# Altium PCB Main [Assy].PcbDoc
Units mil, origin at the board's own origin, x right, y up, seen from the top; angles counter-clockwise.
Board outline 6300 x 4291.34 mil, 4 copper layers (Top Layer, MidLayer1, MidLayer2, Bottom Layer), stack 62.529 mil thick; 0 components, 266 nets, 0 pads, 0 vias.
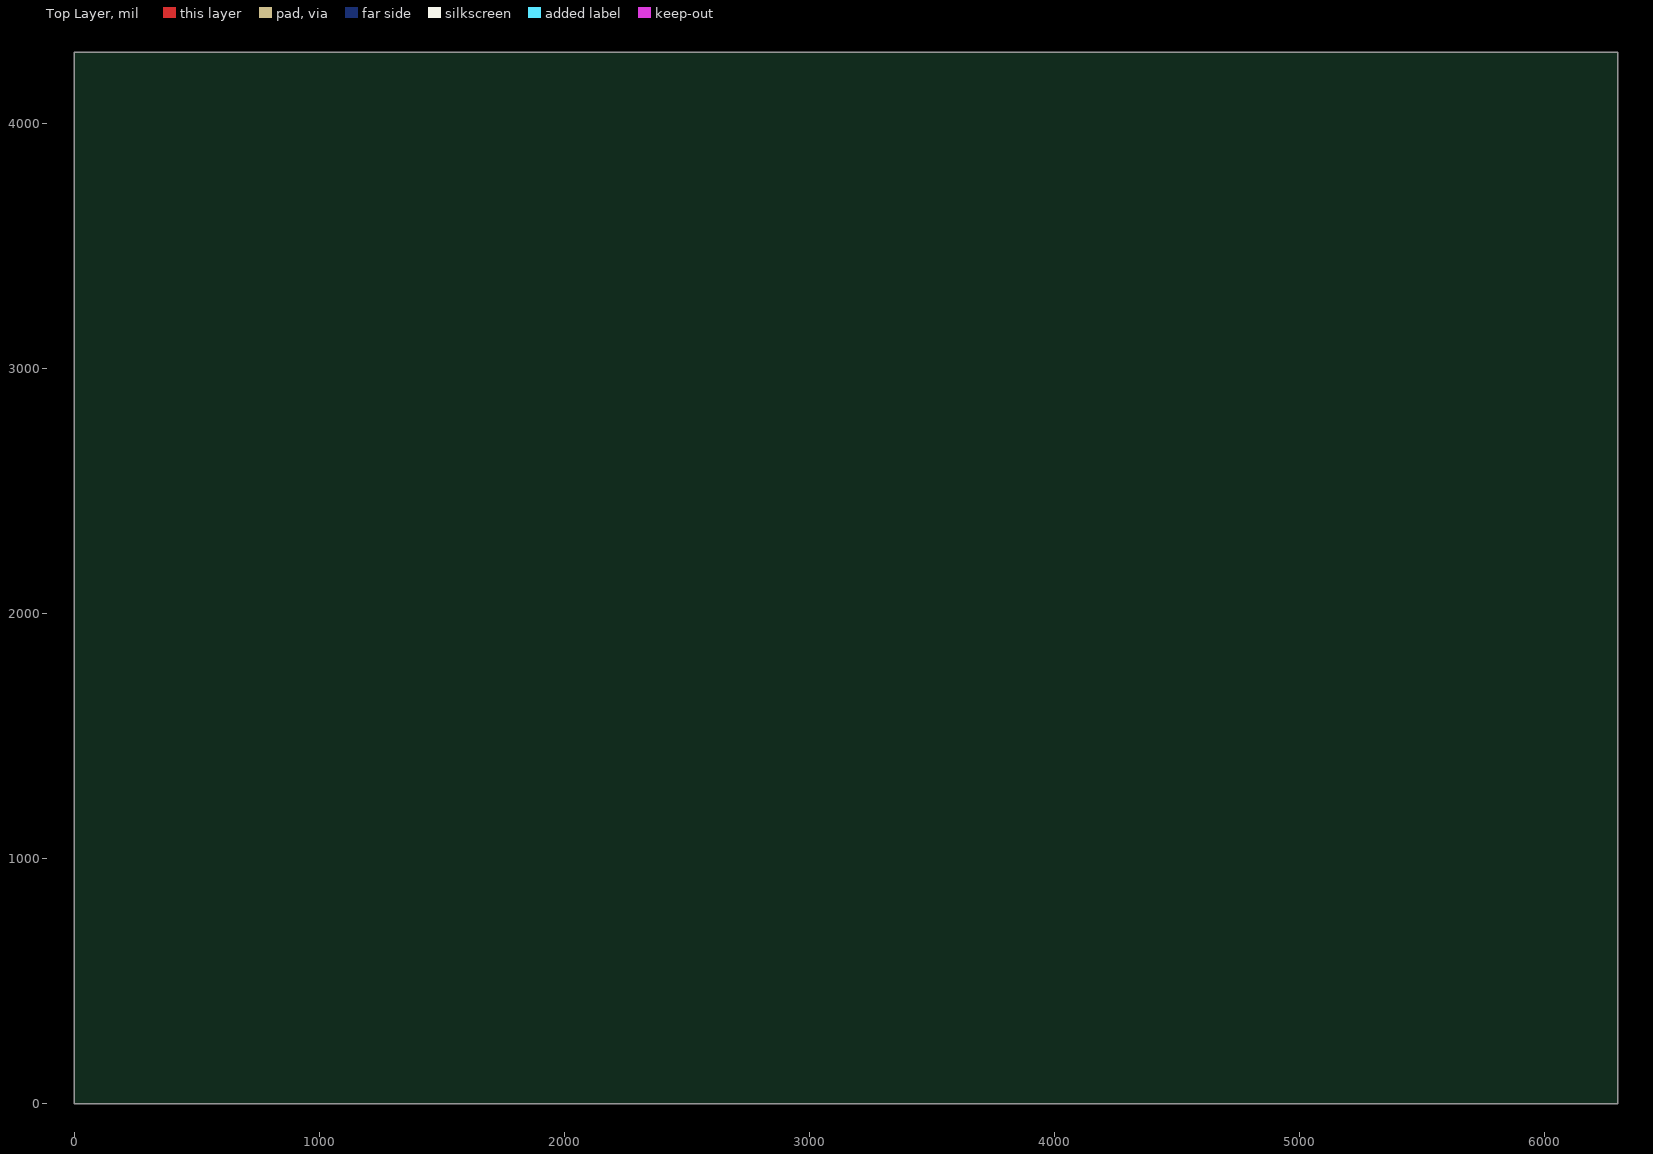
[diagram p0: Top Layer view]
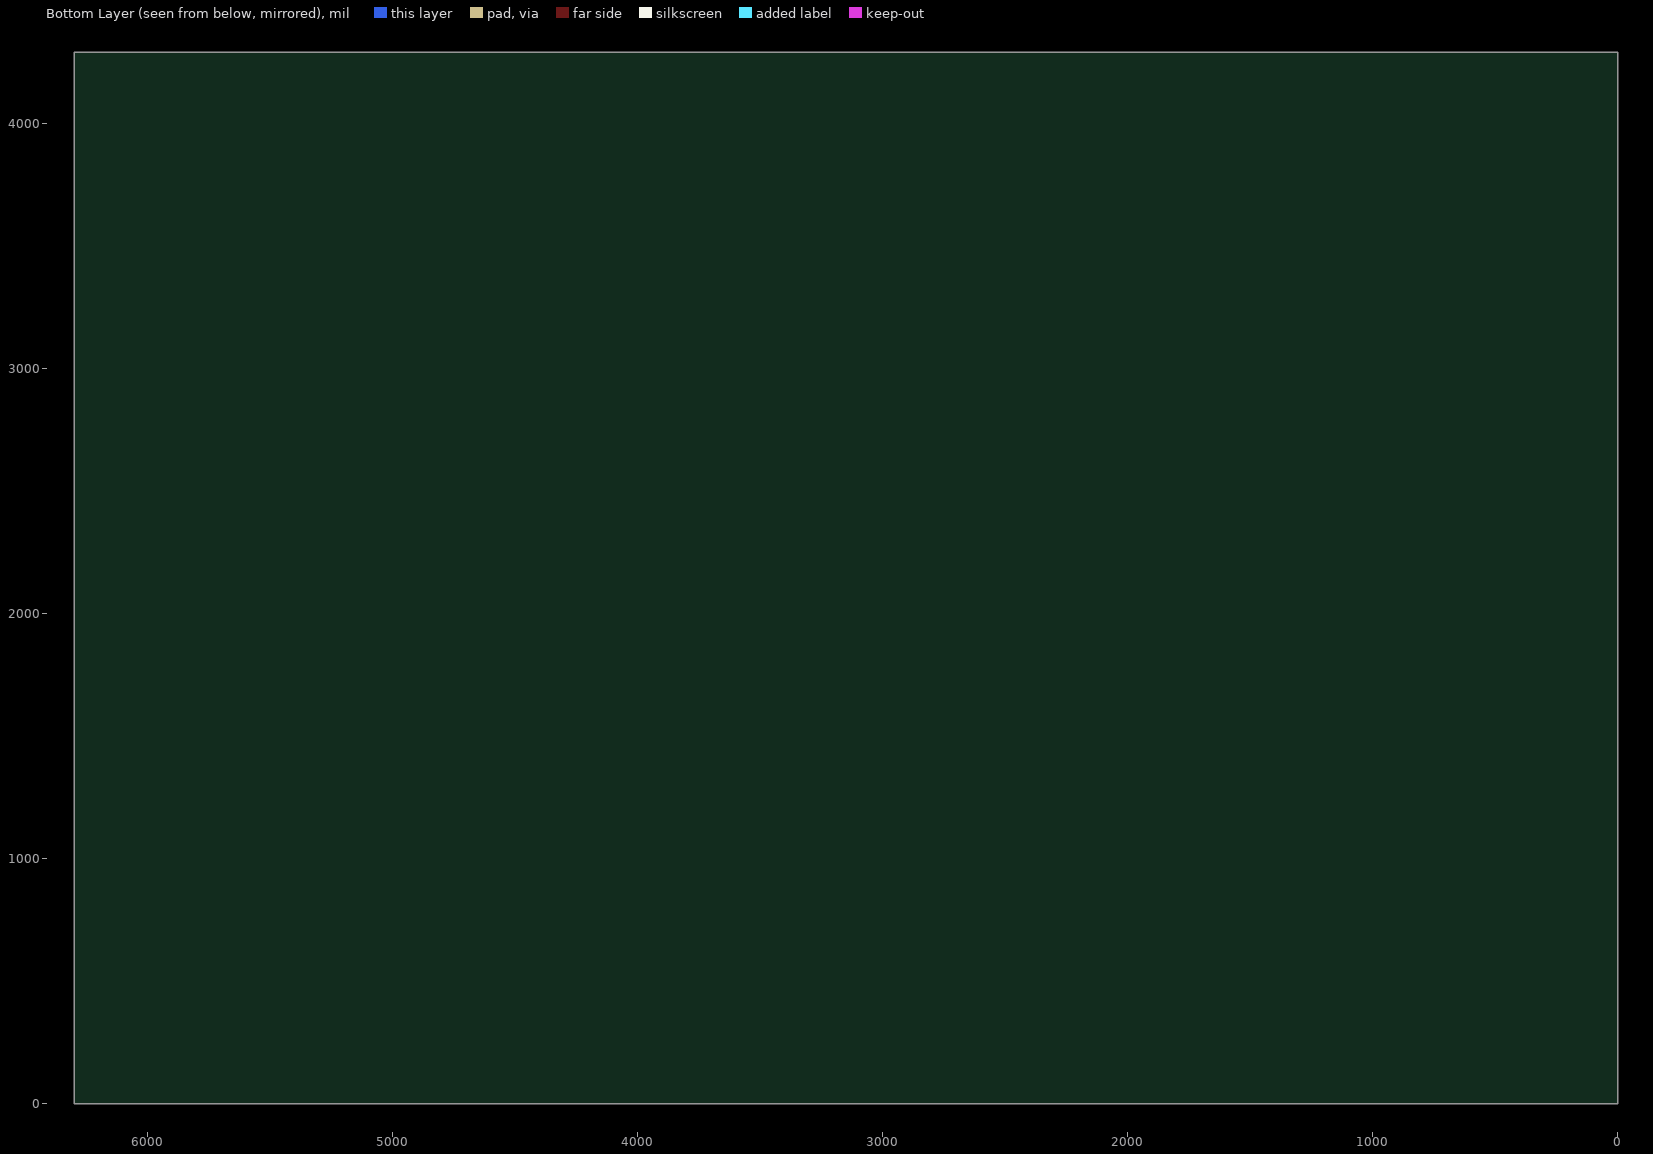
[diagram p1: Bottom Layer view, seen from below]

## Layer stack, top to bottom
Top Layer: signal copper 1.4
Dielectric: prepreg 9.3701, FR-4, Dk 4.2
MidLayer1: signal copper 1.4
Dielectric: core 38.189, FR-4, Dk 4.8
MidLayer2: signal copper 1.4
Dielectric: prepreg 9.3701, FR-4, Dk 4.8
Bottom Layer: signal copper 1.4

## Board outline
0,0 0,4291.34 6300,4291.34 6300,0

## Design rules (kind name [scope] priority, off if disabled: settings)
Clearance Clearance_1 [InNamedPolygon('Top - GND')] p1: gap=7
Clearance [All] p2: gap=7
FabricationTestPointUsage TestPointUsage [All] p1: valid=0 allowmultiple=FALSE
FabricationTestpoint Testpoint [All] p1: side=3 testpointundercomponent=TRUE minsize=40 maxsize=100 preferedsize=60 minholesize=0 maxholesize=40 preferedholesize=32 testpointgrid=1 allowsidetop=TRUE allowsidebottom=TRUE usegrid=TRUE gridtolerance=0.01
HoleSize [All] p1: absolutevalues=TRUE maxlimit=196.85 minlimit=9.84 maxpercent=80.000 minpercent=20.000
PlaneClearance [All] p1: clearance=19.68
PolygonConnect PolygonConnectVia [All vs isvia] p1: connectstyle=Direct reliefconductorwidth=9.84 reliefentries=4 polygonreliefangle="90 Angle" airgapwidth=10
PolygonConnect [All] p2: connectstyle=Relief reliefconductorwidth=15.75 reliefentries=4 polygonreliefangle="90 Angle" airgapwidth=10
RoutingCorners [All] p1: cornerstyle=45-Degree minsetback=98.43 maxsetback=98.43
RoutingLayers [All] p1: top layer_v5=TRUE mid layer 1_v5=FALSE mid layer 2_v5=FALSE bottom layer_v5=TRUE
RoutingVias [All] p1: holewidth=11.81 width=27.56 viastyle="Through Hole" minholewidth=11.81 minwidth=27.56 maxholewidth=11.81 maxwidth=27.56
SilkToSolderMaskClearance SilkscreenOverComponentPads [IsPad] p1: minsilkscreentomaskgap=10 clearancetoexposedcopper=TRUE
SolderMaskExpansion [All] p1: expansion=1.97
Width "Width_High Power" [InNetClass('High Power')] p1: maxlimit=59.06 minlimit=19.68 preferedwidth=39.37
Width Width_Power [InNetClass('Power')] p2: maxlimit=39.37 minlimit=11.81 preferedwidth=19.68
Width [All] p3: maxlimit=100 minlimit=7 preferedwidth=8
21 further rules are at their usual default settings.

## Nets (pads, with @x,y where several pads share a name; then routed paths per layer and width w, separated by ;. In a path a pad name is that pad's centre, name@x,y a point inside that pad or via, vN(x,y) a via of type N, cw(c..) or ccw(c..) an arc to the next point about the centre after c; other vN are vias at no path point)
3V3: 
3V3A: 
3V3UC: 
3V3USB: 
+5V: 
+5VUSB: 
BUZZER: 
C1: 
C2: 
C3: 
DIGI_ANODE1: 
DIGI_ANODE2: 
DIGI_ANODE3: 
DIGI_ANODE4: 
DIGI_CATHODE1: 
DIGI_CATHODE2: 
DIGI_CATHODE3: 
DIGI_CATHODE4: 
GND: 
ICD_NMCLR: 
IDC_PGC: 
IDC_PGD: 
NetANT_1: 
NetBUZ1_1: 
NetBUZ1_2: 
NetC2_1: 
NetC3_1: 
NetC5_1: 
NetC5_2: 
NetC8_1: 
NetC8_2: 
NetC30_1: 
NetC31_1: 
NetC32_1: 
NetC33_1: 
NetC34_1: 
NetC35_1: 
NetC36_1: 
NetC37_1: 
NetC38_1: 
NetC39_1: 
NetC40_1: 
NetC41_1: 
NetC42_1: 
NetC43_1: 
NetC45_1: 
NetC67_1: 
NetC68_1: 
NetC69_1: 
NetC78_1: 
NetC79_1: 
NetC80_1: 
NetC83_1: 
NetC84_1: 
NetC85_1: 
NetC86_1: 
NetD1_1: 
NetD2_1: 
NetD6_1: 
NetD10_1: 
NetD15_2: 
NetD16_2: 
NetD18_2: 
NetD19_3: 
NetD21_2: 
NetD23_2: 
NetGPS1_9: 
NetGPS1_20: 
NetGPS1_21: 
NetGPS1_22: 
NetJ5_2: 
NetJ5_3: 
NetJ7_2: 
NetJ7_3: 
NetJ8_2: 
NetJ8_3: 
NetJ11_1: 
NetLCD1_3: 
NetLCD1_4: 
NetLCD1_5: 
NetLCD1_6: 
NetLCD1_7: 
NetLCD1_8: 
NetLCD1_9: 
NetLCD1_10: 
NetLCD1_11: 
NetLCD1_12: 
NetLCD1_13: 
NetLCD1_14: 
NetLCD1_15: 
NetLCD1_16: 
NetLCD1_17: 
NetLCD-SPR1_1: 
NetLCD-SPR2_1: 
NetLED1_2: 
NetLED2_2: 
NetLED3_2: 
NetLED4_1: 
NetLED5_1: 
NetP2_1: 
NetP2_2: 
NetP2_3: 
NetP2_4: 
NetP2_5: 
NetP2_6: 
NetP3_9: 
NetP3_10: 
NetP3_11: 
NetP3_14: 
NetP3_15: 
NetP3_16: 
NetP3_17: 
NetP3_18: 
NetP3_19: 
NetP3_20: 
NetP3_21: 
NetP3_22: 
NetP3_23: 
NetP3_24: 
NetP3_25: 
NetP3_26: 
NetP3_27: 
NetP3_28: 
NetP3_29: 
NetP3_30: 
NetP3_31: 
NetP3_32: 
NetP3_33: 
NetP3_34: 
NetP4_9: 
NetP4_10: 
NetP4_11: 
NetP4_12: 
NetP4_13: 
NetP4_14: 
NetP4_15: 
NetP4_16: 
NetP4_17: 
NetP4_18: 
NetP4_19: 
NetP4_20: 
NetP4_21: 
NetP4_22: 
NetP4_23: 
NetP4_24: 
NetP4_25: 
NetP4_26: 
NetP4_27: 
NetP4_28: 
NetP4_29: 
NetP4_30: 
NetP4_31: 
NetP4_32: 
NetP4_33: 
NetP5_2: 
NetP5_4: 
NetQ1_1: 
NetQ2_1: 
NetQ3_1: 
NetQ4_1: 
NetQ4_3: 
NetQ5_1: 
NetQ6_1: 
NetQ6_3: 
NetQ7_1: 
NetQ8_1: 
NetQ8_3: 
NetQ9_1: 
NetQ9_3: 
NetQ10_1: 
NetQ11_1: 
NetQ11_3: 
NetQ12_1: 
NetQ12_3: 
NetQ13_1: 
NetQ13_2: 
NetQ14_1: 
NetQ14_2: 
NetQ16_1: 
NetQ16_3: 
NetQ17_1: 
NetQ17_3: 
NetQ18_1: 
NetQ18_3: 
NetQ19_1: 
NetQ20_1: 
NetQ20_3: 
NetQ21_1: 
NetQ22_1: 
NetR3_2: 
NetR6_1: 
NetR9_2: 
NetR20_2: 
NetR23_2: 
NetR28_2: 
NetR31_2: 
NetR32_2: 
NetR36_2: 
NetR39_2: 
NetR44_2: 
NetR47_2: 
NetR53_1: 
NetR57_2: 
NetR60_2: 
NetR67_1: 
NetR69_2: 
NetR73_1: 
NetR74_2: 
NetR93_1: 
NetR103_1: 
NetR106_1: 
NetR109_2: 
NetR110_2: 
NetR111_2: 
NetR112_1: 
NetR113_2: 
NetR114_1: 
NetR115_1: 
NetR119_1: 
NetR120_1: 
NetR121_2: 
NetR122_2: 
NetR124_2: 
NetR125_2: 
NetR126_2: 
NetR127_2: 
NetR128_2: 
NetSD1_2: 
NetSD1_3: 
NetSD1_5: 
NetSD1_7: 
NetU3_49: 
NetU3_53: 
NetU3_54: 
NetU3_55: 
NetU3_57: 
NetU3_60: 
NetU3_61: 
NetU3_62: 
NetU3_65: 
NetU3_66: 
NetU3_67: 
NetU3_68: 
NetU3_69: 
NetU3_70: 
NetU3_71: 
NetU3_72: 
NetU3_128: 
NetU3_136: 
NetU3_137: 
NFLASH_CS0: 
NFLASH_CS1: 
NFLASH_CS2: 
NFLASH_CS3: 
NFLASH_CS4: 
NFLASH_CS5: 
NFLASH_CS6: 
NFLASH_CS7: 
R1: 
R2: 
R3: 
R4: 
VIN: 
VPROTECTED: 
VSLAVES: 
VSWITCHED: 

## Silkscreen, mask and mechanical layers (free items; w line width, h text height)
Top Assy 1:
  circle w4.92: c0.04,-0.63 r78.74
  lines w7.87: -1691.61,-1861.3 552.49,-1861.3 ; -1199.48,-2058.15 -1199.48,-1861.3 ; -590.51,393.07 -511.77,393.07 ; -590.51,786.77 -511.77,786.77 ; -590.51,1179.37 -590.51,3935 ; -590.51,1180.47 -511.77,1180.47 ; -590.51,1574.17 -511.77,1574.17 ; -590.51,1966.77 -590.51,4328.98 -511.77,4328.98 ; -590.51,1967.87 -511.77,1967.87 ; -590.51,2361.58 -511.77,2361.58 ; -590.51,2755 -590.51,-0.63 -511.77,-0.63 ; -590.51,2755.28 -511.77,2755.28 ; -590.51,3147.87 -511.77,3147.87 ; -590.51,3541.58 -511.77,3541.58 ; -590.51,3935.28 -511.77,3935.28 ; -118.07,-0.63 -39.33,-0.63 ; 0.04,-512.44 0.04,-591.18 3540,-591.18 ; 0.04,-118.74 0.04,-40 ; 393.74,-591.18 393.74,-512.44 ; 552.49,-1664.45 4332.01,-1664.45 7914.69,-1664.45 ; 552.49,-1467.6 4332.01,-1467.6 ; 552.49,-1270.75 4332.01,-1270.75 ; 552.49,-1073.9 4332.01,-1073.9 ; 787.44,-591.18 787.44,-512.44 ; 1181.14,-591.18 1181.14,-512.44 ; 1182.41,-2058.15 1182.41,-877.05 ; 1574.84,-591.18 1574.84,-512.44 ; 1812.33,-877.05 1812.33,-2058.15 1812.33,-1861.3 ; 1968.54,-591.18 1968.54,-512.44 ; 2362.24,-591.18 2362.24,-512.44 ; 2442.25,-2058.15 2442.25,-877.05 ; 2755.94,-591.18 2755.94,-512.44 ; 3072.17,-2058.15 3072.17,-877.05 ; 3149.65,-591.18 3149.65,-512.44 ; 3543.35,-512.44 3543.35,-591.18 6692.95,-591.18 6692.95,-512.44 ; 3702.1,-2058.15 3702.1,-877.05 ; 3937.05,-591.18 3937.05,-512.44 ; 4330.75,-591.18 4330.75,-512.44 ; 4724.45,-591.18 4724.45,-512.44 ; 5040.68,-2058.15 5040.68,-1664.45 ; 5118.15,-591.18 5118.15,-512.44 ; 5511.85,-591.18 5511.85,-512.44 ; 5905.55,-591.18 5905.55,-512.44 ; 6299.25,-591.18 6299.25,-512.44 ; 6536.74,-2058.15 6536.74,-1664.45 ; 7048.55,-2058.15 7048.55,-1664.45 ; 7914.69,-1861.3 4332.01,-1861.3 3702.1,-1861.3 3072.17,-1861.3 2442.25,-1861.3 1812.33,-1861.3 ; 552.49,-2058.15 552.49,-1861.3 ; 552.49,-2058.15 552.49,-1861.3 ; 552.49,-2058.15 552.49,-1861.3 ; 552.49,-1861.3 1182.41,-1861.3 1812.33,-1861.3 ; 552.49,-1861.3 552.49,-877.05 ; 552.49,-877.05 4332.01,-877.05 ; 552.49,-877.05 -77.43,-877.05 -1691.61,-877.05 -1691.61,-2058.15 4332.01,-2058.15 ; 4332.01,-2058.15 7914.69,-2058.15 7914.69,-877.05 4332.01,-877.05 ; 4332.01,-2058.15 4332.01,-877.05
  text "ASSEMBLY INSTRUCTION" at 1535,5300 h150
  text "1." at 1300,4950 h150
  text "PLEASE MARK THE \"ISSUE\" BLOCK, ON THE PCB, WITH A" at 1535,4950 h150
  text "PERMANENT-MARKER, AS INDICATED BELOW:" at 1535,4800 h150
  text "ISSUE:" at 1529.16,4650 h150
  text ".Version_PCB Assy Instruction" at 1999.16,4643.43 h157.48
  text "110" at -472.4,4289.61 h98.43
  text "100" at -472.4,3895.91 h98.43
  text "90" at -472.4,3502.21 h98.43
  text "80" at -472.4,3108.5 h98.43
  text "70" at -472.4,2715.91 h98.43
  text "60" at -472.4,2322.21 h98.43
  text "50" at -472.4,1928.5 h98.43
  text "40" at -472.4,1534.8 h98.43
  text "30" at -472.4,1141.1 h98.43
  text "20" at -472.4,747.4 h98.43
  text "10" at -472.4,353.7 h98.43
  text "0" at -472.4,-40 h98.43
  text "0" at 39.41,-473.07 h98.43 r90
  text "10" at 433.11,-473.07 h98.43 r90
  text "20" at 826.81,-473.07 h98.43 r90
  text "30" at 1220.51,-473.07 h98.43 r90
  text "40" at 1614.21,-473.07 h98.43 r90
  text "50" at 2007.91,-473.07 h98.43 r90
  text "60" at 2401.61,-473.07 h98.43 r90
  text "70" at 2795.31,-473.07 h98.43 r90
  text "80" at 3189.02,-473.07 h98.43 r90
  text "90" at 3582.72,-473.07 h98.43 r90
  text "100" at 3976.42,-473.07 h98.43 r90
  text "110" at 4370.12,-473.07 h98.43 r90
  text "120" at 4763.82,-473.07 h98.43 r90
  text "130" at 5157.52,-473.07 h98.43 r90
  text "140" at 5551.22,-473.07 h98.43 r90
  text "150" at 5944.92,-473.07 h98.43 r90
  text "160" at 6338.62,-473.07 h98.43 r90
  text "170" at 6732.32,-473.07 h98.43 r90
  text "TITLE" at 4410.76,-995.16 h98.43
  text "AGRIGEL" at -1525.28,-1248.07 h393.7
  text ".PCB_TITLE" at 4528.87,-1310.12 h196.85
  text "TOP SIDE PLACEMENT" at 4528.87,-1467.6 h98.43
  text ".PCB_Drawn" at 709.97,-1782.56 h98.43
  text ".PCB_Checked" at 1300.52,-1782.56 h98.43
  text ".PCB_Approved" at 1930.44,-1782.56 h98.43
  text ".PRINT_DATE" at 2560.36,-1782.56 h98.43
  text ".PCB_DocRevision" at 3300,-1782.56 h98.43
  text ".PCB_ECRNo" at 3859.57,-1782.56 h98.43
  text "DWG NUMBER" at 4371.39,-1782.56 h98.43
  text ".PCB_Drawing Number" at 5119.42,-1782.56 h98.43
  text "PCB VER" at 6576.11,-1782.56 h98.43
  text "SHEET NO." at 7127.29,-1782.56 h98.43
  text "PLOTFILE" at -1652.24,-1979.41 h98.43
  text ".PCB_Plot File [Assy]" at -1160.11,-1979.41 h98.43
  text "DRAWN" at 709.97,-1979.41 h98.43
  text "CHECKED" at 1300.52,-1979.41 h98.43
  text "APPROVED" at 1891.07,-1979.41 h98.43
  text "DATE" at 2639.1,-1979.41 h98.43
  text "DOC REV." at 3190.28,-1979.41 h98.43
  text "ECR NO." at 3859.57,-1979.41 h98.43
  text "SOURCE" at 4371.39,-1979.41 h98.43
  text ".Pcb_File_Name_No_Path" at 5119.42,-1979.41 h98.43
  text ".Version" at 6654.85,-1979.41 h98.43
  text "SHEET" at 7127.29,-1979.41 h98.43
  text "1" at 7481.62,-1979.41 h98.43
  text "OF" at 7599.73,-1979.41 h98.43
  text "1" at 7796.58,-1979.41 h98.43

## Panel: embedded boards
"Main.PcbDoc" at 0,0, 1 rows x 1 columns, spacing 4291.34 x 1500, rotation 0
